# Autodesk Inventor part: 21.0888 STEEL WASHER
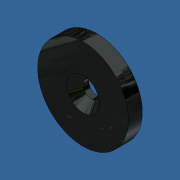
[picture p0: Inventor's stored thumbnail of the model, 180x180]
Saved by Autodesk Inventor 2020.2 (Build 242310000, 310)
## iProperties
Created: 2020-06
Part Number: 21.0888 STEEL WASHER
Material: Stainless Steel AISI 440C, Welded
Document SubType Name: Modeling
Designer: amoles
Mass: 6.98836 g
Surface Area: 7.81078 cm^2
Volume: 0.895943 cm^3
Density: 7.8 g/cm^3
Appearance: Gunmetal - Polished
Author: amoles
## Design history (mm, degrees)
sketch "Sketch1"
  geometry: C1 r 9.75 at (0, 0); 1 further point
  constraints: 1 centre point, 1 coincident
  dimensions: "d0" = 19.5 diameter of C1
extrude "Extrusion1" new body sketch "Sketch1" distance "d1" = 3; taper "d2" = 0 deg
sketch "Sketch2"
  geometry: C1 r 9.75 at (0, 0) reference; 1 further point
  constraints: 1 coincident
hole "Hole1" sketch "Sketch2" at (0, 0) diameter "d3" = 3.5; stored, may be unused: countersink angle "d7" = 90 deg, drill point angle "d9" = 118 deg; dims "d4" = 6, "d5" = 7, "d6" = 2, "d8" = 8
body "Solid1"
